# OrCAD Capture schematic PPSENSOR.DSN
size A
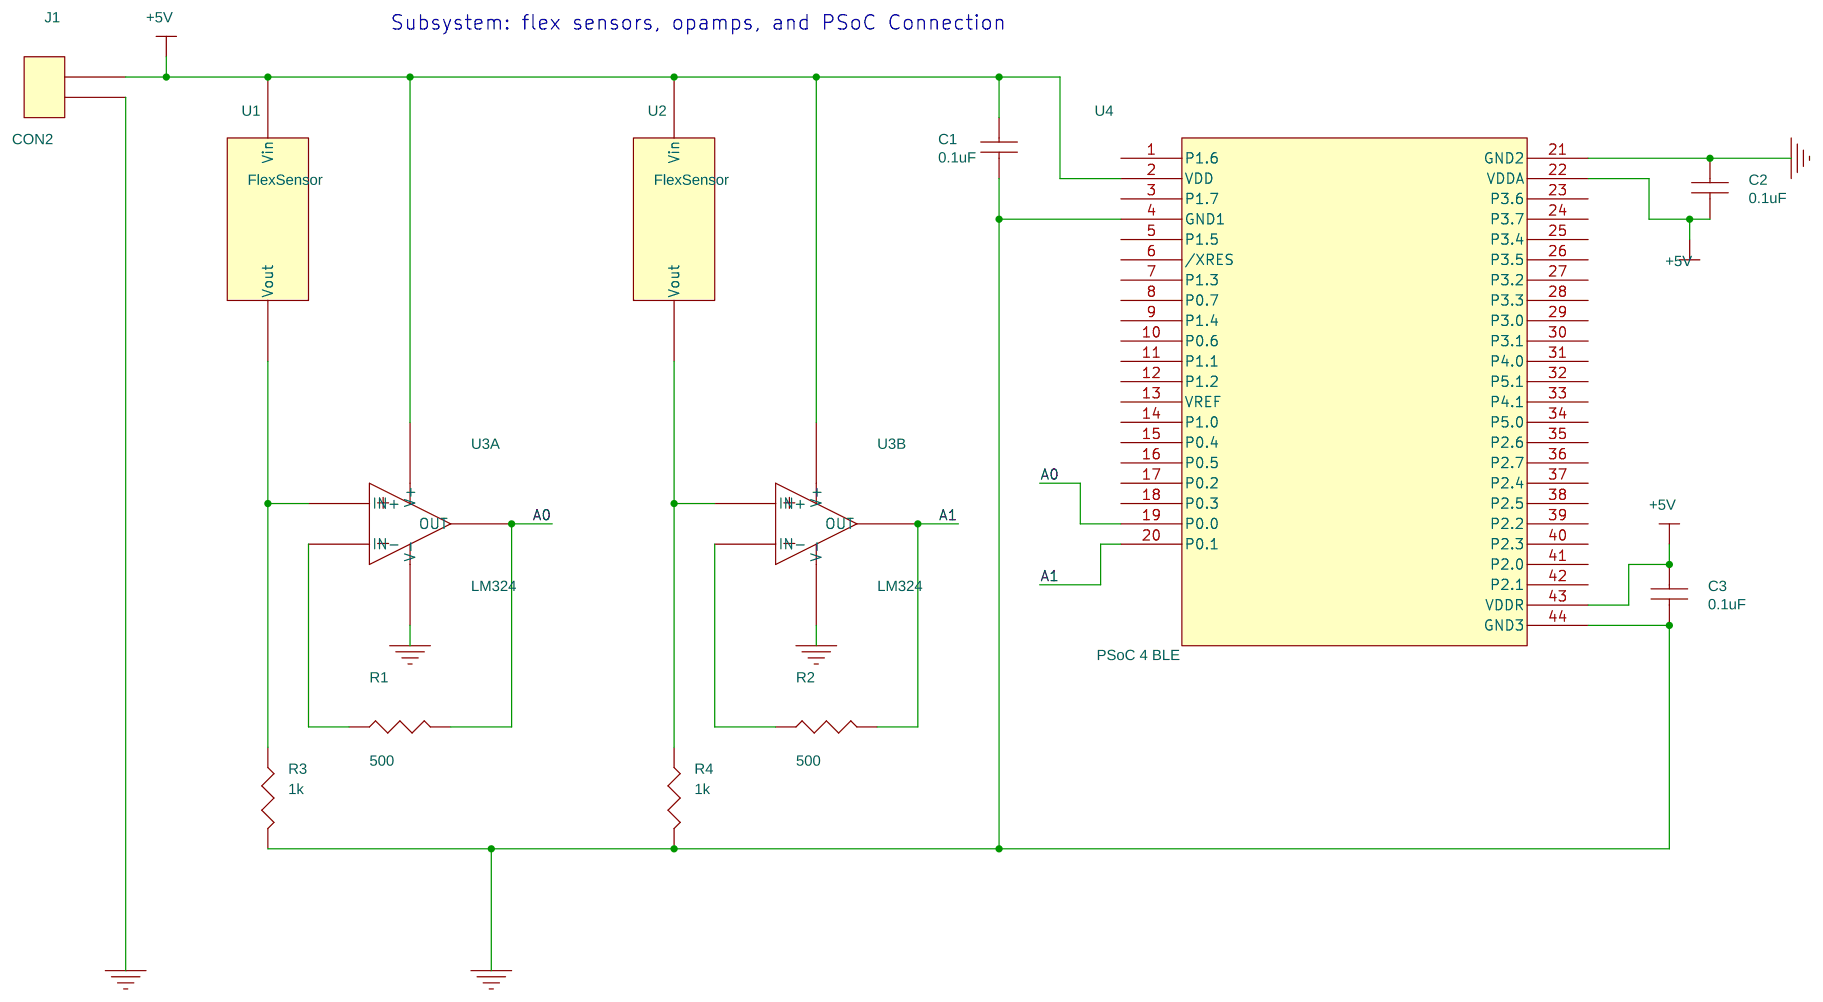
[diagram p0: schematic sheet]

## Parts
C1  0.1uF  [Capacitor]
C2  0.1uF  [Capacitor]
C3  0.1uF  [Capacitor]
J1  CON2  [2pinheader]
R1  500  [Resistor]
R2  500  [Resistor]
R3  1k  [Resistor]
R4  1k  [Resistor]
U1  FlexSensor  [2pinheader]
U2  FlexSensor  [2pinheader]
U3  LM324  [LM324AN]  (sections A,B)
U4  PSoC 4 BLE  [PSOC4BLE]

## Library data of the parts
C1-C3 = CAP_NP
J1 = CON2
R1 R2 = R
R3 R4 = RESISTOR
U1 = FlexSensor_4_1
U2 = FlexSensor_4
U3 = LM324
U4 = PSoC_4_BLE

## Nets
+5V: C1.1 C2.2 C3.1 J1.1 U1.Vin U2.Vin U3.4(V+) U4.2(VDD) U4.22(VDDA) U4.43(VDDR)
GND: C1.2 C2.1 C3.2 J1.2 R3.2 R4.2 U3.11(V-) U4.4(GND1) U4.21(GND2) U4.44(GND3)
A0: R1.2 U3.1(OUT) U4.19(P0.0)
A1: R2.2 U3.7(OUT) U4.20(P0.1)
N04951: R3.1 U1.Vout U3.3(IN+)
N04995: R4.1 U2.Vout U3.5(IN+)
N06521: R1.1 U3.2(IN-)
N09660: R2.1 U3.6(IN-)

Not connected (* = marked no-connect by the designer): U4 1(P1.6) 3(P1.7) 5(P1.5) 6(/XRES) 7(P1.3) 8(P0.7) 9(P1.4) 10(P0.6) 11(P1.1) 12(P1.2) 13(VREF) 14(P1.0) 15(P0.4) 16(P0.5) 17(P0.2) 18(P0.3) 23(P3.6) 24(P3.7) 25(P3.4) 26(P3.5) 27(P3.2) 28(P3.3) 29(P3.0) 30(P3.1) 31(P4.0) 32(P5.1) 33(P4.1) 34(P5.0) 35(P2.6) 36(P2.7) 37(P2.4) 38(P2.5) 39(P2.2) 40(P2.3) 41(P2.0) 42(P2.1)

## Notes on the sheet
- Subsystem: flex sensors, opamps, and PSoC Connection
